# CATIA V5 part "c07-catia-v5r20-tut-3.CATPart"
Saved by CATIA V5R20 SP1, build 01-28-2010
Part number: Part1
Bounding box of the stored display mesh (mm): x 0 to 108, y -52.5 to 52.5, z -52.5 to 52.5
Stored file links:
  D:\v5_r20\psrt_files_downloaded\c07-catia-v5r20-prt\c07-catia-v5r20-tut-3.CATPart
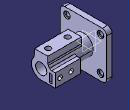
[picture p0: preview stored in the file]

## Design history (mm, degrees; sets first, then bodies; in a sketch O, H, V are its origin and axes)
Body1 (main body)
  Sketch1 on yz-plane, origin (0, 0, 0), H (0, 1, 0), V (0, 0, 1)
    line L1 (52.5, 42.5) -> (52.5, -42.5)
    line L2 (42.5, -52.5) -> (-42.5, -52.5)
    line L3 (-52.5, -42.5) -> (-52.5, 42.5)
    line L4 (-42.5, 52.5) -> (42.5, 52.5)
    point P1 (52.5, 52.5)
    point P2 (52.5, -52.5)
    point P3 (-52.5, -52.5)
    arc A1 centre (42.5, 42.5) radius 10 from (52.5, 42.5) to (42.5, 52.5) ccw
    arc A2 centre (42.5, -42.5) radius 10 from (52.5, -42.5) to (42.5, -52.5) cw
    arc A3 centre (-42.5, -42.5) radius 10 from (-42.5, -52.5) to (-52.5, -42.5) cw
    arc A4 centre (-42.5, 42.5) radius 10 from (-52.5, 42.5) to (-42.5, 52.5) cw
    distance P1 P2 = 105
    radius A1 = 10
    distance P2 P3 = 105
    radius A2 = 10
    radius A3 = 10
    radius A4 = 10
    vertical: L1 V, L3 V
    horizontal: L2 H, L4 H
    equidistance: L1 L3 O, L2 L4 O
    coincidence: L1 P1, L4 P1, L1 P2, L2 P2, L2 P3, L3 P3
    tangency: A1 L1, A1 L4, A2 L1, A2 L2, A3 L2, A3 L3, A4 L3, A4 L4
  Pad1: profile Sketch1, direction (1, 0, 0), length 12
  Sketch2 on face of Pad1, origin (12, 0, 0), H (0, 1, 0), V (0, 0, 1)
    circle A1 centre (0, 0) radius 22
    radius A1 = 22
  Pad2: profile Sketch2, direction (1, 0, 0), length 96
  Sketch3 on face of Pad2, origin (108, 0, 0), H (0, 1, 0), V (0, 0, 1)
    point P1 (-15, 16.0935)
    line L1 (-15, 16.0935) -> (-15, 32)
    line L2 (-15, 32) -> (15, 32)
    line L3 (15, 32) -> (15, 16.0935)
    point P4 (15, 16.0935)
    axis line L4 (0, 0) -> (0, 32)
    point P5 (0, 32)
    reference projected circle E1 centre (0, 0) radius 22 from edge [face of Pad2 | face of Pad2]
    reference projected circle E2 centre (0, 0) radius 22 from edge [face of Pad2 | face of Pad2]
    projected circle E3 centre (0, 0) radius 22 from edge [face of Pad2 | face of Pad2]
    projected arc E4 centre (0, 0) radius 22 from (15, 16.0935) to (-15, 16.0935) ccw from edge [face of Pad2 | face of Pad2]
    length L2 = 30
    distance H L2 = 32
    vertical: L1 V, L3 V, L4 V
    horizontal: L2 H
    midpoint: P5 L2
    coincidence: P4 E1, P1 E2
  Pad3: profile Sketch3, direction (-1, 0, 0), length 76
  Sketch4 on face of Pad2, origin (108, 0, 0), H (0, 1, 0), V (0, 0, 1)
    point P1 (0, -22)
    line L1 (0, -22) -> (32, -22)
    line L2 (32, -22) -> (32, 8)
    line L3 (32, 8) -> (20.4939, 8)
    point P4 (20.4939, 8)
    reference projected circle E1 centre (0, 0) radius 22 from edge of Pad2
    reference projected circle E2 centre (0, 0) radius 22 from edge [face of Pad2 | face of Pad2]
    reference projected circle E3 centre (0, 0) radius 22 from edge [face of Pad2 | face of Pad2]
    projected arc E4 centre (0, 0) radius 22 from (-15, 16.0935) to (15, 16.0935) ccw from edge of Pad3
    projected arc E5 centre (0, 0) radius 22 from (0, -22) to (20.4939, 8) ccw from edge of Pad3
    length L2 = 30
    distance V L2 = 32
    coincidence: P1 V, P4 E1, P1 E2
    horizontal: L1 H, L3 H
    vertical: L2 V
    tangency: L1 E3
  Pad4: profile Sketch4, direction (-1, 0, 0), length 57
  Sketch5 on face of Pad2, origin (108, 0, 0), H (0, 1, 0), V (0, 0, 1)
    line L1 (18.5, 1.5) -> (24.5, 1.5)
    line L2 (24.5, 1.5) -> (24.5, -17.5)
    line L3 (24.5, -17.5) -> (18.5, -17.5)
    line L4 (18.5, -17.5) -> (18.5, 1.5)
    reference projected line E1 (52.5, -42.5) -> (52.5, 42.5) from edge [face of Pad1 | face of Pad1]
    reference projected line E2 (-42.5, -52.5) -> (42.5, -52.5) from edge [face of Pad1 | face of Pad1]
    length L3 = 6
    length L2 = 19
    distance L4 E1 = 34
    distance L3 E2 = 35
    horizontal: L1 H, L3 H
    vertical: L2 V, L4 V
  Pocket1: profile Sketch5, direction (-1, 0, 0), length 50
  Sketch6 on face of Pad2, origin (108, 0, 0), H (0, 1, 0), V (0, 0, 1)
    point P1 (0, 0)
    coincidence: P1 O
  Hole1: placed by Sketch6, at (108, 0, 0) direction (-1, 0, 0), diameter 25, depth 82, V-bottom angle 120
  Sketch7 on face of Pad3, origin (90.7325, -5.9449, 32), H (1, 0, 0), V (0, 1, 0)
    point P1 (1.2675, 5.9449)
    reference projected line E1 (17.2675, -9.0551) -> (-58.7325, -9.0551) from edge [face of Pad3 | face of Pad3]
    reference projected line E2 (17.2675, 20.9449) -> (17.2675, -9.0551) from edge [face of Pad3 | face of Pad3]
    distance P1 E1 = 15
    distance P1 E2 = 16
  Hole2: placed by Sketch7, at (92, 0, 32) direction (0, 0, -1), diameter 12, depth 33.0037, threaded, thread diameter 13.2, thread depth 10, pitch 1
  RectPattern1: of Hole2, direction 1 instances 2, spacing 44, along edge [face of Pad3 | face of Pad3]
  Sketch8 on face of Pad4, origin (86.2721, 32, -2.7131), H (1, 0, 0), V (0, 0, -1)
    point P1 (10.7279, 4.2869)
    reference projected line E1 (21.7279, 19.2869) -> (-35.2721, 19.2869) from edge [face of Pad4 | face of Pad4]
    reference projected line E2 (21.7279, 19.2869) -> (21.7279, -10.7131) from edge [face of Pad4 | face of Pad4]
    distance P1 E1 = 15
    distance E2 P1 = 11
  Hole3: placed by Sketch8, at (97, 32, -7) direction (0, -1, 0), diameter 10, through (limit type 6), threaded, thread diameter 11, thread depth 7.5, pitch 1
  RectPattern2: of Hole3, direction 1 instances 2, spacing 25, along edge [face of Pad4 | face of Pad4], direction 2 instances 2, spacing 76
  Sketch9 on face of Pad1, origin (12, -36.1764, 22.8739), H (0, 1, 0), V (0, 0, 1)
    point P1 (-1.3236, -60.3739)
    reference projected line E1 (-16.3236, 19.6261) -> (-16.3236, -65.3739) from edge [face of Pad1 | face of Pad1]
    reference projected line E2 (-6.3236, -75.3739) -> (78.6764, -75.3739) from edge [face of Pad1 | face of Pad1]
    distance P1 E1 = 15
    distance E2 P1 = 15
  Hole4: placed by Sketch9, at (12, -37.5, -37.5) direction (-1, 0, 0), diameter 10, through (limit type 3), counterbore diameter 15, counterbore depth 3
  RectPattern3: of Hole4, direction 1 instances 2, spacing 76, along edge [face of Pad1 | face of Pad1], direction 2 instances 2, spacing 76, along edge [face of Pad1 | face of Pad1] reversed
  Fillet1: radius 15, on edge [face of Pad3 | face of Pad2]
  Fillet2: radius 5, on edge [face of Pad2 | face of Pad3]; edge [face of Pad2 | face of Pad4]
